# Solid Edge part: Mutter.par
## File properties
Sűrűség: 0,000 kg/m^3
Pontosság: 0,990
Author: bmolnar
Last saved by: ahadarics
Revision: 77
Username: bmolnar
Dokumentum tartalom típus: 0
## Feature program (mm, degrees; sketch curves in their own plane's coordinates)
base feature "unnamed BaseFeature 1"
thread "unnamed Thread 1"
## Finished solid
Body 1: solid body, 23 faces, 46 edges, 24 vertices.
  Faces by surface: cone 14, plane 8, cylinder 1
  Edges by curve: spline 24, circle 16, line 6
Bounding box of the edges (mm): 7.000 x 21.939 x 19.000, from (0, -10.9697, -9.5) to (7, 10.9697, 9.5).
Cylindrical faces by radius (mm): R5.3235 x1
Conical faces (half-angle, radius in mm at the cone's reference point): 60 deg R5.6618 x2, 60 deg R10.2348 x12
Planar faces by outward normal: +x 1, +z 1, -x 1, -z 1, oblique 4
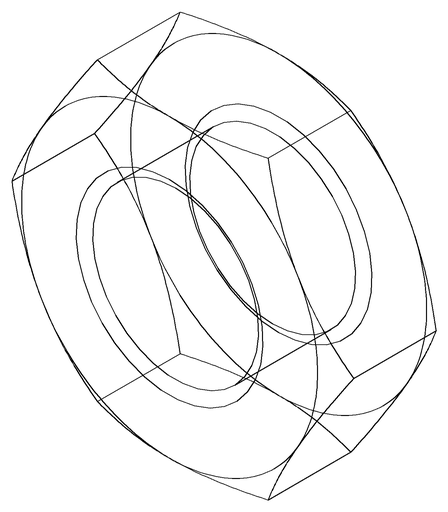
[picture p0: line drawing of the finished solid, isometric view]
